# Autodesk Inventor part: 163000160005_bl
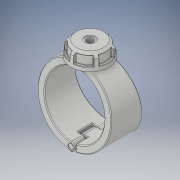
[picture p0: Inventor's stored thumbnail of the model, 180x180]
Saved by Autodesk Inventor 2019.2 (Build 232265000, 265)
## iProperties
Created: 2022-02
Part Number: 163000160005_bl
Material: Generic
Description: Plassadle Threaded 160x1/2''
Document SubType Name: Modeling
Designer: comp2
Density: 1 g/cm^3
Appearance: Default
Author: comp2
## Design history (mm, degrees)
derived "16300.ipt"
feature "Solid1::16300.ipt" dims "ScaleForDerivedMember" = 10
feature "Solid2::16300.ipt" dims "ScaleForDerivedMember" = 10
feature "Solid3::16300.ipt" dims "ScaleForDerivedMember" = 10
feature "Solid4::16300.ipt" dims "ScaleForDerivedMember" = 10
tag "TaggingFeature1"
body "Solid1"
body "Solid2"
body "Solid3"
body "Solid4"
other parameters: "d2" = 197 [user parameter], "d7" = 187.15 [user parameter], "d8" = 85 deg [user parameter], "d9" = 45 deg [user parameter], "d10" = 102 [user parameter], "d11" = 49 [user parameter], "d12" = 27.2895 [user parameter], "d13" = 42.84 [user parameter], "d14" = 27.9465 [user parameter], "d42" = 3.7 [user parameter], "d49" = 3.94 [user parameter], "d50" = 106 [user parameter], "d51" = 0 [user parameter], "d52" = 25.9 [user parameter], "d53" = 108.35 [user parameter], "d54" = 37.1 [user parameter], "d55" = 0 [user parameter], "d56" = 21.2 [user parameter], "d57" = 21.2 [user parameter], "d59" = 0 [user parameter], "d60" = 106 [user parameter], "d61" = 0 [user parameter], "d62" = 37.1 [user parameter], "d63" = 0 [user parameter], "d65" = 0 [user parameter], "d67" = 0 [user parameter], "d69" = 0 [user parameter], "d70" = 1 [user parameter], "d71" = 101.76 [user parameter], "d72" = 0 [user parameter], "d73" = 2 [user parameter], "d78" = 86.7 [user parameter], "d79" = 5.1 [user parameter], "d80" = 60 deg [user parameter], "d81" = 5.1 [user parameter], "d84" = 0 [user parameter], "d85" = 1 [user parameter], "d87" = 360 deg [user parameter], "d122" = 49 [user parameter], "d124" = 42.80128 [user parameter], "d125" = 1.94925 [user parameter], "d127" = 235 [user parameter], "d129" = 18.631 [user parameter], "d130" = 15.83635 [user parameter], "d131" = 31.85 [user parameter], "d132" = 45 deg [user parameter], "d133" = 22.295 [user parameter], "d134" = 9.3155 [user parameter], "d136" = 0 [user parameter], "d138" = 0 [user parameter], "d1" = 25 [user parameter], "B" = 197 [user parameter], "L" = 106 [user parameter], "E_" = 54 [user parameter], "E1" = 102 [user parameter], "H1" = 235 [user parameter], "H2" = 49 [user parameter], "H3" = 78 [user parameter], "H_costum" = 49 [user parameter], "Rp" = 18.631 [user parameter], "d128" = 38.985 [user parameter]
